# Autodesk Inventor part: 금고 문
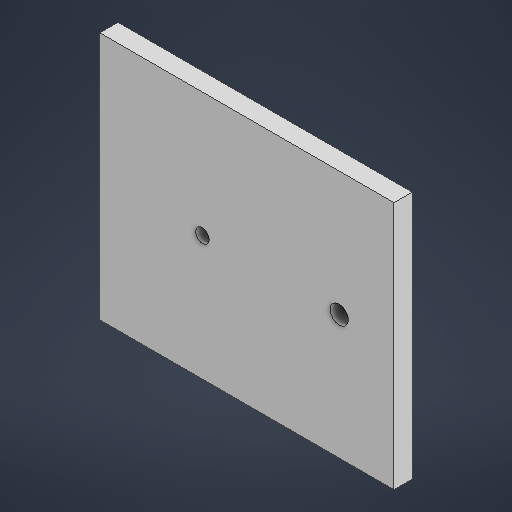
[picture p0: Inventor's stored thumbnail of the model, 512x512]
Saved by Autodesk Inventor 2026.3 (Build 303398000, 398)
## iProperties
Created: 2026-08
Part Number: 금고 문
Material: 일반
Document SubType Name: Modeling
Designer: chang
Density: 1 g/cm^3
Appearance: 기본값
Author: chang
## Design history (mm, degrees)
sketch "스케치1"
  geometry: L1 (0, 0)-(0, 109); L2 (0, 109)-(129, 109); L3 (129, 109)-(129, 0); L4 (129, 0)-(0, 0)
  constraints: 8 end point, 3 perpendicular, 1 vertical
  dimensions: "d0" = 109 distance of L1.start L1.end; "d1" = 129 distance of L1.end L2.end
extrude "돌출1" new body sketch "스케치1" distance "d2" = 8; taper "d3" = 0 deg
sketch "스케치2"
  geometry: C1 r 3 at (45, 54.5); 1 further point
  constraints: 1 centre point
  dimensions: "d4" = 6 diameter of C1
extrude "돌출2" cut sketch "스케치2" distance "d5" = 8; taper "d6" = 0 deg
sketch "스케치3"
  geometry: C1 r 4 at (105, 54.5); 1 further point
  constraints: 1 centre point
  dimensions: "d7" = 8 diameter of C1
extrude "돌출3" cut sketch "스케치3" distance "d8" = 8; taper "d9" = 0 deg
node "솔리드1"
